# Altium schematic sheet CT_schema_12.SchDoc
size 389 x 385 mm
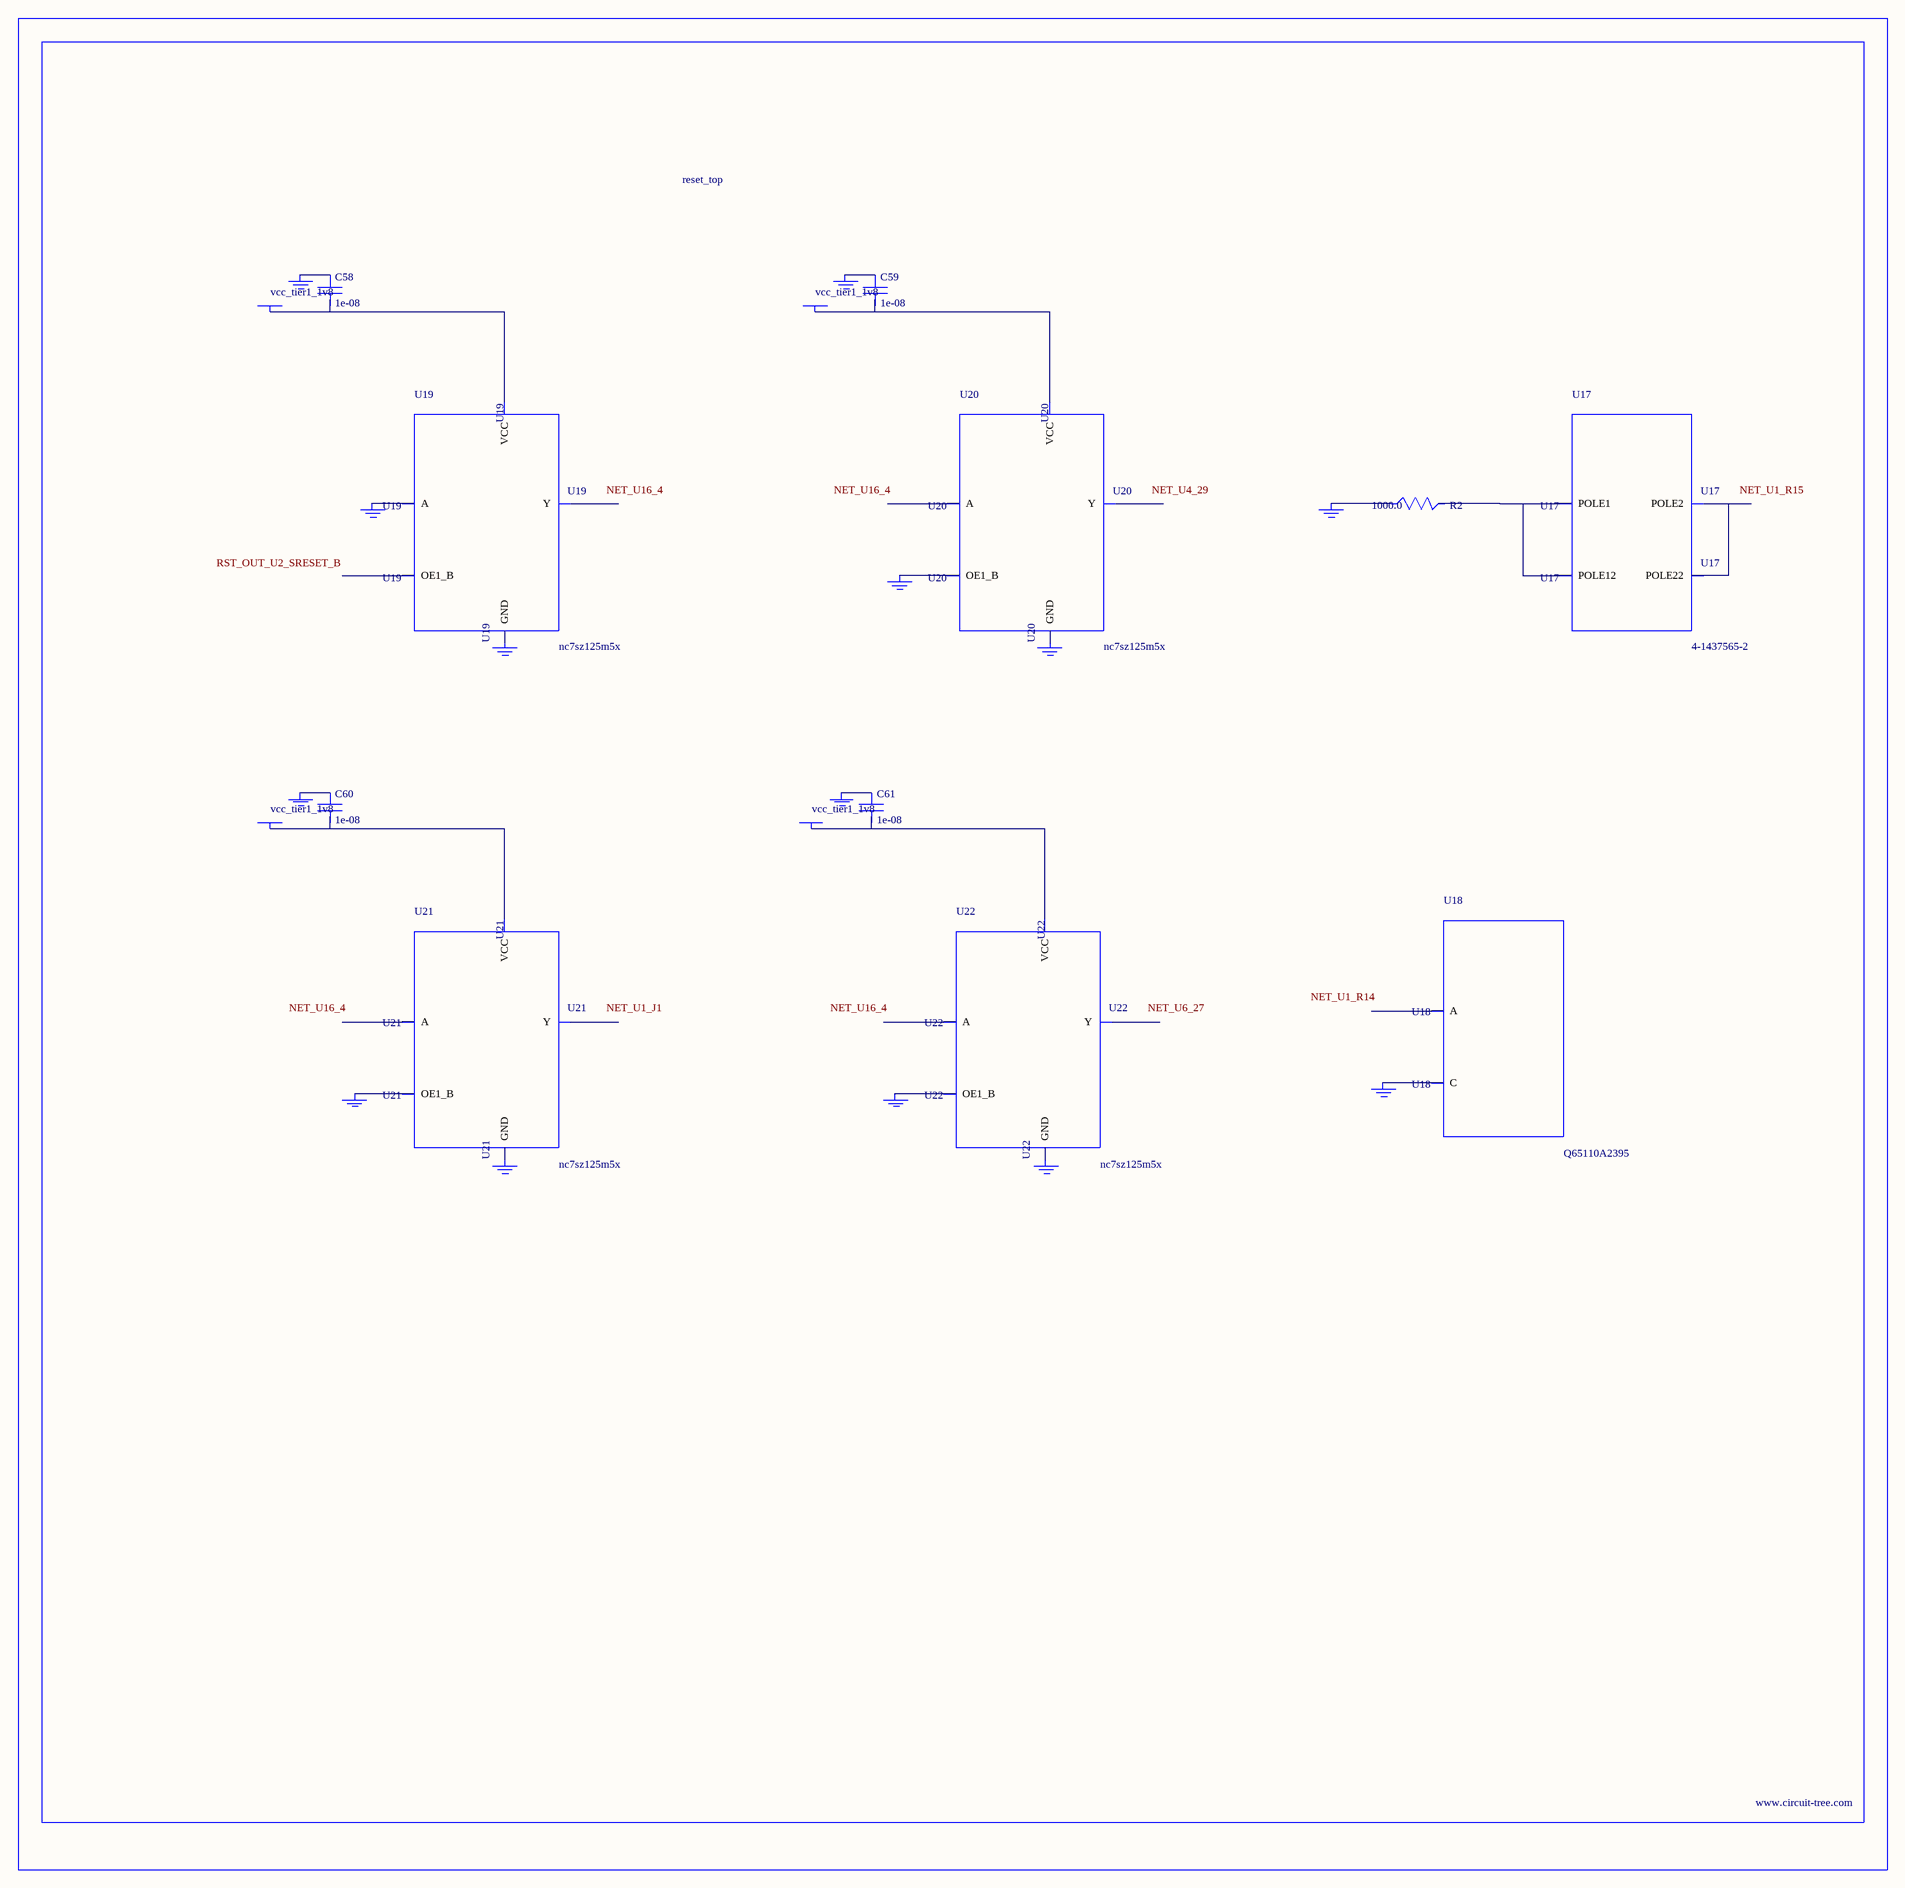
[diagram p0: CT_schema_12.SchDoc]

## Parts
BORDER11  (no value)
C58  1e-08  [C0402]
C59  1e-08  [C0402]
C60  1e-08  [C0402]
C61  1e-08  [C0402]
GND_INSTANCE_11_0  (no value)
GND_INSTANCE_11_1  (no value)
GND_INSTANCE_11_2  (no value)
GND_INSTANCE_11_3  (no value)
GND_INSTANCE_11_4  (no value)
GND_INSTANCE_11_5  (no value)
GND_INSTANCE_11_6  (no value)
GND_INSTANCE_11_7  (no value)
GND_INSTANCE_11_8  (no value)
GND_INSTANCE_11_9  (no value)
GND_INSTANCE_11_10  (no value)
GND_INSTANCE_11_11  (no value)
GND_INSTANCE_11_12  (no value)
GND_INSTANCE_11_13  (no value)
POWER_INSTANCE_11_0  vcc_tier1_1v8
POWER_INSTANCE_11_1  vcc_tier1_1v8
POWER_INSTANCE_11_2  vcc_tier1_1v8
POWER_INSTANCE_11_3  vcc_tier1_1v8
R2  1000.0  [R0603]
U17  4-1437565-2  [SW_4-1437565-2]
U18  Q65110A2395  [LGM67K-G1J2-24-Z]
U19  nc7sz125m5x  [NC7SZ125M5X]
U20  nc7sz125m5x  [NC7SZ125M5X]
U21  nc7sz125m5x  [NC7SZ125M5X]
U22  nc7sz125m5x  [NC7SZ125M5X]

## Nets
NetC58_1: C58.1 GND_INSTANCE_11_2.0(GND)
NetC58_2: C58.2 POWER_INSTANCE_11_0.0(PWR) U19.5(VCC)
NetC59_1: C59.1 GND_INSTANCE_11_5.0(GND)
NetC59_2: C59.2 POWER_INSTANCE_11_1.0(PWR) U20.5(VCC)
NetC60_1: C60.1 GND_INSTANCE_11_8.0(GND)
NetC60_2: C60.2 POWER_INSTANCE_11_2.0(PWR) U21.5(VCC)
NetC61_1: C61.1 GND_INSTANCE_11_11.0(GND)
NetC61_2: C61.2 POWER_INSTANCE_11_3.0(PWR) U22.5(VCC)
NetGND_INSTANCE_11_0_0: GND_INSTANCE_11_0.0(GND) R2.1
NetGND_INSTANCE_11_1_0: GND_INSTANCE_11_1.0(GND) U18.C
NetGND_INSTANCE_11_3_0: GND_INSTANCE_11_3.0(GND) U19.2(A)
NetGND_INSTANCE_11_4_0: GND_INSTANCE_11_4.0(GND) U19.3(GND)
NetGND_INSTANCE_11_6_0: GND_INSTANCE_11_6.0(GND) U20.1(OE1_B)
NetGND_INSTANCE_11_7_0: GND_INSTANCE_11_7.0(GND) U20.3(GND)
NetGND_INSTANCE_11_9_0: GND_INSTANCE_11_9.0(GND) U21.1(OE1_B)
NetGND_INSTANCE_11_10_0: GND_INSTANCE_11_10.0(GND) U21.3(GND)
NetGND_INSTANCE_11_12_0: GND_INSTANCE_11_12.0(GND) U22.1(OE1_B)
NetGND_INSTANCE_11_13_0: GND_INSTANCE_11_13.0(GND) U22.3(GND)
NetR2_2: R2.2 U17.1(POLE1) U17.2(POLE12)
NetU17_3: U17.3(POLE2) U17.4(POLE22)

Not connected (* = marked no-connect by the designer): U18 A; U19 1(OE1_B) 4(Y); U20 2(A) 4(Y); U21 2(A) 4(Y); U22 2(A) 4(Y)

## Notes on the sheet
- Labels drawn without touching a wire or pin: NET_U1_J1, NET_U1_R14, NET_U1_R15, NET_U4_29, NET_U6_27, NET_U16_4, RST_OUT_U2_SRESET_B

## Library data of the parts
BORDER11 = BORDER_PAGE11
C58-C61 = C0402C103K3RAC
GND_INSTANCE_11_0-GND_INSTANCE_11_13 = GND
POWER_INSTANCE_11_0-POWER_INSTANCE_11_3 = PWR
R2 = RC0603JR-071KL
